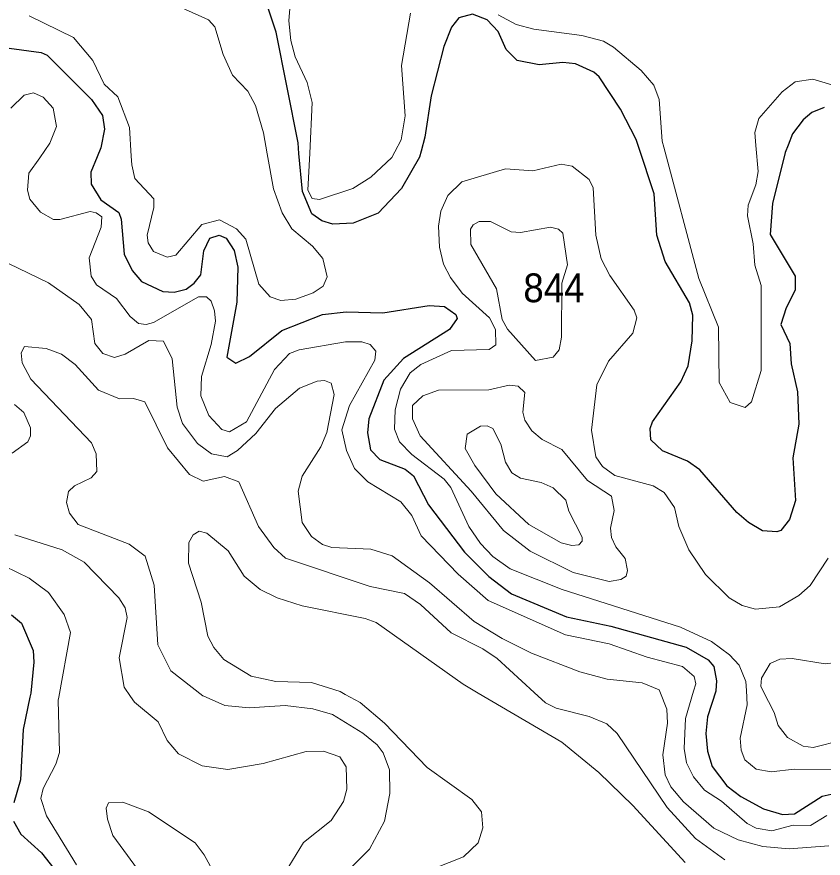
# Model space of a CAD drawing. Extents: x 473.9 to 500, y 7733.1 to 7760.8.
# Drawn here: x 488.002 to 490.243, y 7749.235 to 7751.572 of the extents above; entities that cross this region are included whole.
import ezdxf

# ---------------------------------------------------------------- set-up
doc = ezdxf.new("R2010")
doc.units = 0
doc.header["$LTSCALE"] = 0.032
doc.layers.add('1', color=7, linetype='Continuous', lineweight=25)
doc.layers.add('2', color=7, linetype='Continuous', lineweight=13)
doc.layers.add('21', color=7, linetype='Continuous')

msp = doc.modelspace()

# ---------------------------------------------------------------- linework, layer by layer
at = {"layer": '1'}
for points in [[(490.2463, 7751.3202), (490.2121, 7751.3062), (490.1879, 7751.2859), (490.1585, 7751.2473), (490.146, 7751.2158), (490.1379, 7751.1955), (490.1027, 7751.053), (490.0959, 7750.9674), (490.1654, 7750.8519), (490.1656, 7750.8123), (490.1405, 7750.7637), (490.1258, 7750.7173), (490.151, 7750.6641), (490.1547, 7750.6084), (490.1721, 7750.5301), (490.1757, 7750.44), (490.1593, 7750.3472), (490.1663, 7750.2281), (490.15, 7750.1758), (490.126, 7750.1455), (490.1141, 7750.1411), (490.0745, 7750.1446), (490.0356, 7750.1672), (490.0036, 7750.1953), (489.9, 7750.3134), (489.866, 7750.3381), (489.7967, 7750.3661), (489.7645, 7750.3973), (489.7628, 7750.4281), (489.7692, 7750.447), (489.8476, 7750.558), (489.868, 7750.6026), (489.8794, 7750.6716), (489.8808, 7750.7436), (489.8714, 7750.7778), (489.8039, 7750.8922), (489.7807, 7750.965), (489.7736, 7751.0803), (489.7307, 7751.2087), (489.7231, 7751.2316), (489.6797, 7751.3154), (489.6203, 7751.4051), (489.6056, 7751.418), (489.5548, 7751.4418), (489.5195, 7751.445), (489.4535, 7751.4387), (489.3927, 7751.451), (489.3618, 7751.4808), (489.3395, 7751.5309), (489.3094, 7751.564), (489.2687, 7751.5793), (489.2303, 7751.5696), (489.21, 7751.5435), (489.1892, 7751.4898), (489.1539, 7751.3522), (489.136, 7751.2373), (489.1254, 7751.1985), (489.121, 7751.1823), (489.071, 7751.0951), (489.0063, 7751.027), (488.9369, 7750.9991), (488.8801, 7750.9963), (488.8496, 7751.0053), (488.822, 7751.025), (488.7957, 7751.0865), (488.7861, 7751.1927), (488.7835, 7751.2222), (488.7226, 7751.5297), (488.6762, 7751.6702)], [(487.9246, 7751.4925), (488.0693, 7751.4728), (488.0865, 7751.4653), (488.2094, 7751.3424), (488.2401, 7751.2981), (488.2458, 7751.2595), (488.2354, 7751.2077), (488.2254, 7751.1832), (488.2079, 7751.1405), (488.2083, 7751.1075), (488.235, 7751.0636), (488.2856, 7751.0282), (488.2923, 7751.0099), (488.3002, 7750.9124), (488.3221, 7750.8673), (488.3481, 7750.8368), (488.4078, 7750.8087), (488.4392, 7750.8068), (488.4726, 7750.8153), (488.4952, 7750.8319), (488.513, 7750.8553), (488.5218, 7750.9219), (488.5384, 7750.9567), (488.5643, 7750.965), (488.5842, 7750.9569), (488.6063, 7750.9227), (488.6163, 7750.8768), (488.6131, 7750.7794), (488.5859, 7750.6266), (488.6103, 7750.6102), (488.6487, 7750.6281), (488.7381, 7750.701), (488.8512, 7750.7455), (488.9174, 7750.7528), (489.0196, 7750.7497), (489.1483, 7750.7704), (489.1904, 7750.7671), (489.2226, 7750.7453), (489.226, 7750.7337), (489.2042, 7750.7033), (489.0767, 7750.6229), (489.0219, 7750.5624), (488.9803, 7750.4553), (488.9766, 7750.416), (488.9851, 7750.3692), (489.0108, 7750.3422), (489.0809, 7750.3153), (489.1047, 7750.2965), (489.1462, 7750.2166), (489.2467, 7750.0853), (489.3141, 7750.0171), (489.3767, 7749.9693), (489.5301, 7749.9057), (489.6535, 7749.8796), (489.8623, 7749.8208), (489.9233, 7749.7858)], [(487.9871, 7749.9104), (488.0151, 7749.8877), (488.0473, 7749.8116), (488.0495, 7749.7795), (488.0405, 7749.6933), (488.0381, 7749.6817), (488.0197, 7749.5926), (488.0124, 7749.4521), (487.9937, 7749.3883)], [(489.9233, 7749.7858), (489.9397, 7749.767), (489.947, 7749.7277), (489.9447, 7749.6995), (489.9446, 7749.6988), (489.9216, 7749.6277), (489.9173, 7749.5813), (489.9222, 7749.5325), (489.9345, 7749.4893), (489.9753, 7749.4356), (490.0143, 7749.4065), (490.077, 7749.3721), (490.1304, 7749.356), (490.1636, 7749.3584), (490.2408, 7749.4074), (490.2823, 7749.4165)], [(487.9924, 7749.3375), (488.0129, 7749.3011), (488.0704, 7749.25), (488.115, 7749.1932)]]:
    msp.add_lwpolyline(points, dxfattribs=at)
at = {"layer": '2'}
for points in [[(488.7652, 7751.6519), (488.7578, 7751.5612), (488.7631, 7751.5061), (488.7757, 7751.4612), (488.8086, 7751.3899), (488.823, 7751.3341), (488.8159, 7751.1932), (488.8108, 7751.0908), (488.8231, 7751.0669), (488.8436, 7751.0641), (488.9357, 7751.0951), (488.9859, 7751.1262), (489.0445, 7751.1814), (489.0528, 7751.1973), (489.0704, 7751.2307), (489.0811, 7751.2966), (489.0707, 7751.437), (489.0963, 7751.5823)], [(488.4064, 7751.6216), (488.5343, 7751.5632), (488.5525, 7751.544), (488.5754, 7751.4676), (488.6012, 7751.4098), (488.6443, 7751.3651), (488.6656, 7751.3255), (488.6877, 7751.2495), (488.6981, 7751.1912), (488.7153, 7751.0945), (488.7398, 7751.0276), (488.7663, 7750.9828), (488.8238, 7750.9353), (488.8525, 7750.9005), (488.8649, 7750.8493), (488.8533, 7750.8242), (488.826, 7750.8054), (488.7778, 7750.7879), (488.7359, 7750.7842), (488.706, 7750.7942), (488.6744, 7750.8293), (488.6381, 7750.954), (488.6129, 7750.9827), (488.5656, 7751.0079), (488.5164, 7750.9951), (488.4438, 7750.9098), (488.4195, 7750.9041), (488.3817, 7750.9201), (488.3669, 7750.9438), (488.364, 7750.9654), (488.3825, 7751.042), (488.383, 7751.0667), (488.3298, 7751.1228), (488.3215, 7751.1609), (488.32, 7751.1848), (488.315, 7751.2648), (488.2826, 7751.3493), (488.2446, 7751.3851), (488.213, 7751.4505), (488.1594, 7751.5146), (488.0366, 7751.5745)], [(489.3401, 7751.5779), (489.3899, 7751.5506), (489.4391, 7751.5374), (489.5721, 7751.5205), (489.6324, 7751.5039), (489.6605, 7751.4881), (489.7374, 7751.4233)], [(489.7374, 7751.4233), (489.7725, 7751.3823), (489.7878, 7751.3421), (489.7962, 7751.2263), (489.8006, 7751.2099), (489.8981, 7750.8453), (489.9525, 7750.7101), (489.9538, 7750.5563), (489.9849, 7750.5009), (490.0266, 7750.4863), (490.044, 7750.5023), (490.0708, 7750.5896), (490.0708, 7750.8259), (490.0535, 7750.8821), (490.0491, 7750.9417), (490.033, 7751.0187), (490.0352, 7751.0485), (490.0563, 7751.1057), (490.0627, 7751.1426), (490.0564, 7751.2143), (490.0532, 7751.2505), (490.0648, 7751.2891), (490.1295, 7751.3638), (490.1655, 7751.3915), (490.2147, 7751.3992), (490.3294, 7751.3642)], [(490.2531, 7749.3537), (490.2084, 7749.3259), (490.1602, 7749.3266), (490.1007, 7749.3105), (490.0572, 7749.3178), (490.0322, 7749.3309), (489.9608, 7749.3933), (489.9131, 7749.4238), (489.8828, 7749.4609), (489.8636, 7749.4994), (489.8569, 7749.5394), (489.8602, 7749.6226), (489.8832, 7749.6989), (489.8892, 7749.7187), (489.8848, 7749.7394), (489.8524, 7749.7671), (489.7543, 7749.793), (489.6487, 7749.8298), (489.527, 7749.8554), (489.3119, 7749.9503), (489.2291, 7750.0242), (489.1261, 7750.1305), (489.0997, 7750.1871), (489.0695, 7750.2249), (488.9772, 7750.2799), (488.9407, 7750.317), (488.9184, 7750.3671), (488.9052, 7750.4251), (488.927, 7750.4921), (488.9971, 7750.6185), (488.9997, 7750.6431), (488.9839, 7750.6617), (488.9605, 7750.6691), (488.9154, 7750.6691), (488.7868, 7750.6466), (488.7599, 7750.6365), (488.7183, 7750.5922), (488.6401, 7750.4468), (488.5929, 7750.4196), (488.5718, 7750.4257), (488.5352, 7750.4641), (488.5136, 7750.5191), (488.515, 7750.573), (488.5422, 7750.6614), (488.5537, 7750.7268), (488.5518, 7750.7557), (488.5419, 7750.782), (488.5288, 7750.7939), (488.5071, 7750.7945), (488.3818, 7750.7233), (488.3611, 7750.7175), (488.3404, 7750.7205), (488.3165, 7750.7392), (488.2786, 7750.7896), (488.2229, 7750.8278), (488.2081, 7750.8518), (488.2032, 7750.9026), (488.2364, 7750.9876), (488.2378, 7751.016), (488.2224, 7751.0277), (488.2057, 7751.0309), (488.1218, 7751.009), (488.1035, 7751.0093), (488.0681, 7751.0295), (488.0383, 7751.0656), (488.0311, 7751.0903), (488.0356, 7751.1374), (488.0656, 7751.1805), (488.094, 7751.2214), (488.1123, 7751.2671), (488.1033, 7751.3178), (488.0747, 7751.3491), (488.0482, 7751.3604), (488.0218, 7751.3546), (487.9852, 7751.3183)], [(490.257, 7750.0681), (490.2067, 7749.9924), (490.1756, 7749.9645), (490.1215, 7749.9328), (490.0555, 7749.9263), (490.0186, 7749.9369), (489.9823, 7749.9581), (489.9161, 7750.023), (489.8696, 7750.0917), (489.8417, 7750.1561), (489.8301, 7750.2088), (489.8014, 7750.2503), (489.7704, 7750.269), (489.6645, 7750.2978), (489.6296, 7750.3225), (489.6117, 7750.3499), (489.5989, 7750.4234), (489.6138, 7750.5498), (489.6467, 7750.6158), (489.714, 7750.6931), (489.7252, 7750.7356), (489.7175, 7750.7573), (489.6505, 7750.8535), (489.6258, 7750.8994), (489.6111, 7750.9653), (489.6035, 7751.0971), (489.5932, 7751.1202), (489.5458, 7751.1572), (489.5147, 7751.1629), (489.4359, 7751.1444), (489.3598, 7751.1495), (489.2393, 7751.1134), (489.2002, 7751.0758), (489.1804, 7751.0321), (489.1736, 7750.99), (489.1768, 7750.9321), (489.1883, 7750.885), (489.2071, 7750.8481), (489.2397, 7750.8048), (489.3158, 7750.7356), (489.3321, 7750.7037), (489.3333, 7750.6607), (489.3149, 7750.6478), (489.2098, 7750.6449), (489.1245, 7750.6065), (489.0956, 7750.5832), (489.068, 7750.5375), (489.0534, 7750.48), (489.0514, 7750.4261), (489.0653, 7750.3916), (489.0999, 7750.356), (489.1902, 7750.2873), (489.2082, 7750.2643), (489.2587, 7750.1563), (489.2905, 7750.1089), (489.3254, 7750.073), (489.3732, 7750.039), (489.5174, 7749.9808), (489.847, 7749.8769), (489.9328, 7749.8365), (489.9826, 7749.8), (490.01, 7749.7706), (490.0282, 7749.7257), (490.0298, 7749.7003), (490.0324, 7749.6604), (490.0122, 7749.5679), (490.0152, 7749.5353), (490.0259, 7749.5079), (490.0572, 7749.4817), (490.0989, 7749.4744), (490.1628, 7749.4824), (490.284, 7749.4809)], [(487.9789, 7750.8865), (488.09, 7750.8334), (488.1753, 7750.7733), (488.2092, 7750.7316), (488.2189, 7750.6646), (488.2411, 7750.6367), (488.2732, 7750.6259), (488.3032, 7750.6353), (488.3688, 7750.6724), (488.4094, 7750.6706), (488.4338, 7750.6217), (488.4474, 7750.4879), (488.462, 7750.4421), (488.5045, 7750.3871), (488.5429, 7750.3577), (488.5866, 7750.3498), (488.6154, 7750.3677), (488.6662, 7750.4143), (488.7209, 7750.4843), (488.7879, 7750.5402), (488.837, 7750.5599), (488.8573, 7750.5614), (488.8758, 7750.554), (488.884, 7750.5231), (488.8632, 7750.4176), (488.8473, 7750.3779), (488.795, 7750.2958), (488.7838, 7750.2541), (488.7955, 7750.1673), (488.8207, 7750.1281), (488.8518, 7750.1061), (488.8774, 7750.0982), (488.9861, 7750.0929), (489.0452, 7750.0744), (489.1486, 7749.9994), (489.2727, 7749.8921), (489.3506, 7749.8447), (489.4323, 7749.8046), (489.5668, 7749.7522), (489.6429, 7749.7318), (489.7398, 7749.7218)], [(489.9701, 7749.2302), (489.8888, 7749.2899), (489.8092, 7749.376), (489.6708, 7749.5809), (489.642, 7749.6083), (489.5924, 7749.6288), (489.5014, 7749.6512), (489.4714, 7749.6661), (489.4402, 7749.6948), (489.3373, 7749.7896), (489.2976, 7749.8163), (489.2096, 7749.8605), (489.1237, 7749.9399), (489.0795, 7749.9705), (488.9841, 7749.9895), (488.7486, 7750.0681), (488.7165, 7750.098), (488.6737, 7750.156), (488.6189, 7750.2807), (488.5796, 7750.2954), (488.5195, 7750.2818), (488.4814, 7750.3002), (488.4204, 7750.3745), (488.3579, 7750.5021), (488.3259, 7750.5115), (488.2873, 7750.5108), (488.2291, 7750.5349), (488.1636, 7750.6065), (488.1262, 7750.6349), (488.0831, 7750.6506), (488.0234, 7750.656), (488.0143, 7750.6389), (488.017, 7750.6106), (488.0409, 7750.565), (488.209, 7750.3886), (488.2227, 7750.3585), (488.2238, 7750.3086), (488.2081, 7750.2913), (488.1619, 7750.2691), (488.1458, 7750.253), (488.1396, 7750.2226), (488.1481, 7750.193), (488.172, 7750.1622), (488.3146, 7750.1069), (488.3583, 7750.0737), (488.384, 7749.993), (488.394, 7749.8279), (488.4299, 7749.7551), (488.519, 7749.6862), (488.52, 7749.6854), (488.5805, 7749.6589), (488.648, 7749.6521), (488.7482, 7749.6593), (488.8249, 7749.6498), (488.8796, 7749.6339), (488.9638, 7749.5824), (489.0034, 7749.5496), (489.0199, 7749.5278), (489.0379, 7749.4807), (489.0384, 7749.4141), (489.0241, 7749.3375), (488.9826, 7749.2602), (488.8927, 7749.1701)], [(487.9886, 7750.3602), (488.0328, 7750.3915), (488.0399, 7750.4077), (488.0399, 7750.4304), (488.0215, 7750.4724), (487.9952, 7750.495)], [(488.3286, 7749.6682), (488.3174, 7749.6843), (488.2998, 7749.7095), (488.286, 7749.7915), (488.3084, 7749.9035), (488.3027, 7749.9303), (488.2855, 7749.958), (488.1887, 7750.0568), (488.1276, 7750.091), (487.9962, 7750.1331)], [(489.8593, 7749.2228), (489.7146, 7749.381), (489.62, 7749.473), (489.5168, 7749.5571), (489.2844, 7749.6933), (489.2425, 7749.7179), (489.0007, 7749.8893), (488.9701, 7749.9005), (488.7948, 7749.936), (488.7258, 7749.9578), (488.6786, 7749.9815), (488.634, 7750.0181), (488.5894, 7750.0883), (488.5304, 7750.1374), (488.5088, 7750.1433), (488.4922, 7750.1333), (488.4798, 7750.1118), (488.4789, 7750.0546), (488.5142, 7749.9464), (488.5329, 7749.8516), (488.5491, 7749.8201), (488.5769, 7749.7864), (488.6533, 7749.7406), (488.7221, 7749.7259), (488.8206, 7749.7232), (488.9005, 7749.6974), (488.9144, 7749.6899), (488.9562, 7749.6672), (489.0237, 7749.6099), (489.1427, 7749.487), (489.2669, 7749.3979), (489.2934, 7749.3632), (489.2973, 7749.3193), (489.2845, 7749.277), (489.2435, 7749.2388), (489.1198, 7749.1893)], [(487.9677, 7750.0462), (488.036, 7750.0126), (488.0898, 7749.9727), (488.1334, 7749.9121), (488.1508, 7749.8619), (488.1186, 7749.6824), (488.1171, 7749.6741), (488.1203, 7749.5283), (488.1104, 7749.4956), (488.0755, 7749.4286), (488.0689, 7749.4002), (488.0844, 7749.3524), (488.1678, 7749.2162)], [(489.7398, 7749.7218), (489.7875, 7749.7025), (489.7892, 7749.6981), (489.8088, 7749.6484), (489.8103, 7749.6103), (489.7976, 7749.5223), (489.8045, 7749.4667), (489.8201, 7749.4327), (489.8552, 7749.3917), (489.9392, 7749.318), (490.0073, 7749.2861), (490.0753, 7749.2672), (490.149, 7749.2605), (490.2593, 7749.2688)], [(488.7474, 7749.1952), (488.7992, 7749.2781), (488.8757, 7749.3397), (488.9095, 7749.3926), (488.9196, 7749.427), (488.9169, 7749.4882), (488.8998, 7749.5168), (488.8544, 7749.5323), (488.8061, 7749.5315), (488.6865, 7749.498), (488.5886, 7749.4809), (488.5168, 7749.4911), (488.4511, 7749.5245), (488.4194, 7749.562), (488.3944, 7749.6135), (488.3286, 7749.6682)], [(488.3574, 7749.1761), (488.2683, 7749.298), (488.2536, 7749.3428), (488.2506, 7749.3734), (488.2569, 7749.3888), (488.2963, 7749.3908), (488.3676, 7749.3639), (488.4973, 7749.2774), (488.523, 7749.2443), (488.5511, 7749.1913)]]:
    msp.add_lwpolyline(points, dxfattribs=at)
for points in [[(489.3657, 7750.7043), (489.3513, 7750.7316), (489.335, 7750.8162), (489.2638, 7750.9396), (489.263, 7750.9819), (489.27, 7750.9937), (489.2875, 7751.0037), (489.3189, 7751.0034), (489.3762, 7750.9748), (489.4022, 7750.9733), (489.4849, 7750.9876), (489.5074, 7750.9825), (489.52, 7750.9707), (489.5328, 7750.8829), (489.5169, 7750.8319), (489.5161, 7750.6819), (489.5092, 7750.6465), (489.4927, 7750.627), (489.4436, 7750.6177)], [(489.517, 7750.3703), (489.4622, 7750.3975), (489.4337, 7750.4221), (489.4144, 7750.4518), (489.4081, 7750.4734), (489.4141, 7750.5283), (489.3954, 7750.5463), (489.3705, 7750.5485), (489.3142, 7750.5358), (489.1743, 7750.5348), (489.1309, 7750.5196), (489.1019, 7750.4922), (489.1015, 7750.4551), (489.1231, 7750.4079), (489.2652, 7750.2543), (489.3545, 7750.1451), (489.4289, 7750.0872), (489.5479, 7750.0285), (489.6482, 7750.0035), (489.6807, 7750.009), (489.6955, 7750.0185), (489.6993, 7750.0343), (489.6929, 7750.0672), (489.667, 7750.0996), (489.6553, 7750.1257), (489.6523, 7750.1517), (489.6625, 7750.201), (489.655, 7750.2403), (489.588, 7750.2836)], [(489.5363, 7750.1984), (489.5283, 7750.2297), (489.493, 7750.2634), (489.459, 7750.2783), (489.4023, 7750.29), (489.3782, 7750.3049), (489.3603, 7750.3351), (489.3476, 7750.3848), (489.3251, 7750.4288), (489.3096, 7750.436), (489.2909, 7750.4352), (489.2534, 7750.4125), (489.2483, 7750.3731), (489.2747, 7750.3257), (489.3333, 7750.2468), (489.4247, 7750.1621), (489.5152, 7750.1107), (489.5442, 7750.1032), (489.5639, 7750.1057), (489.5737, 7750.1154), (489.5735, 7750.1264)], [(490.3103, 7749.782), (490.2491, 7749.7744), (490.1568, 7749.7896), (490.1226, 7749.7879), (490.0957, 7749.7758), (490.0715, 7749.7352), (490.07, 7749.7122), (490.0758, 7749.7007), (490.1068, 7749.6398), (490.1181, 7749.6031), (490.1439, 7749.5704), (490.1875, 7749.5461), (490.2158, 7749.5419), (490.457, 7749.6031), (490.495, 7749.6347), (490.4975, 7749.6549), (490.4823, 7749.6746), (490.4062, 7749.7038), (490.3912, 7749.7096), (490.3738, 7749.7256), (490.3405, 7749.7762)]]:
    msp.add_lwpolyline(points, close=True, dxfattribs=at)

# ---------------------------------------------------------------- texts
at = {"layer": '21', "width": 0.95}
msp.add_text('844', height=0.08, dxfattribs=at).set_placement((489.41, 7750.7792))

doc.saveas('drawing.dxf')
